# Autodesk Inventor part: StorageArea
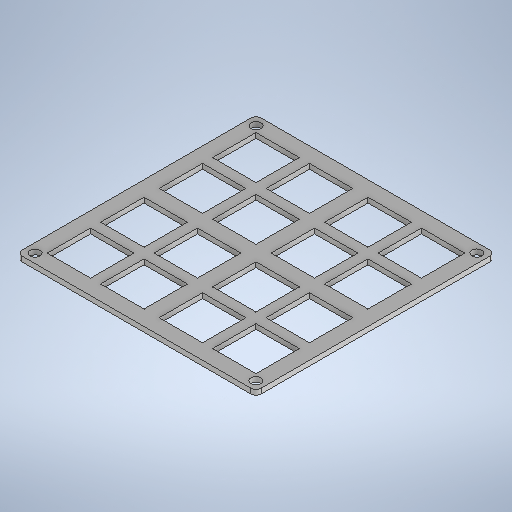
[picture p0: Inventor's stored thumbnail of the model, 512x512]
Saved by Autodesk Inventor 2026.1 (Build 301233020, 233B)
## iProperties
Created: 2026-10
Part Number: StorageArea
Material: Generic
Document SubType Name: Modeling
Designer: hp
Density: 1 g/cm^3
Appearance: Default
d6: 43.000 mm
d7: 43.000 mm
d20: 5.000 mm
d21: 0.00 deg
d26: 2.000 ul
d28: 111.000 mm
d29: 2.000 ul
d31: 111.000 mm
d34: 2.000 ul
d36: 53.000 mm
d37: 2.000 ul
d39: 53.000 mm
StorageThickness: 15.000 mm
d43: 15.000 mm
d44: 15.000 mm
d45: 15.000 mm
d46: 5.000 mm
d47: 10.000 mm
d48: 9.000 mm
d49: 9.000 mm
d51: 10.000 mm
d52: 0.00 deg
Author: hp
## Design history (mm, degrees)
sketch "Sketch1"
  geometry: L1 (-103.5, 60.5)-(-60.5, 60.5); L2 (-60.5, 60.5)-(-60.5, 103.5); L3 (-60.5, 103.5)-(-103.5, 103.5); L4 (-103.5, 103.5)-(-103.5, 60.5); L5 (-103.5, -50.5)-(-60.5, -50.5); L6 (-60.5, -50.5)-(-60.5, -7.5); L7 (-60.5, -7.5)-(-103.5, -7.5); L8 (-103.5, -7.5)-(-103.5, -50.5); L9 (7.5, 60.5)-(50.5, 60.5); L10 (50.5, 60.5)-(50.5, 103.5); L11 (50.5, 103.5)-(7.5, 103.5); L12 (7.5, 103.5)-(7.5, 60.5); L13 (7.5, -50.5)-(50.5, -50.5); L14 (50.5, -50.5)-(50.5, -7.5); L15 (50.5, -7.5)-(7.5, -7.5); L16 (7.5, -7.5)-(7.5, -50.5); L17 (7.5, -103.5)-(50.5, -103.5); L18 (50.5, -103.5)-(50.5, -60.5); L19 (-103.5, 7.5)-(-60.5, 7.5); L20 (7.5, -60.5)-(7.5, -103.5); L21 (-60.5, -103.5)-(-60.5, -60.5); L22 (-60.5, -60.5)-(-103.5, -60.5); L23 (-103.5, -103.5)-(-60.5, -103.5); L24 (-103.5, -60.5)-(-103.5, -103.5); L25 (-103.5, 50.5)-(-103.5, 7.5); L26 (-60.5, 50.5)-(-103.5, 50.5); L27 (-60.5, 7.5)-(-60.5, 50.5); L28 (50.5, -60.5)-(7.5, -60.5); L29 (7.5, 7.5)-(50.5, 7.5); L30 (7.5, 50.5)-(7.5, 7.5); L31 (50.5, 50.5)-(7.5, 50.5); L32 (50.5, 7.5)-(50.5, 50.5); L33 (60.5, -50.5)-(103.5, -50.5); L34 (103.5, -50.5)-(103.5, -7.5); L35 (-50.5, 60.5)-(-7.5, 60.5); L36 (60.5, -7.5)-(60.5, -50.5); L37 (-7.5, -50.5)-(-7.5, -7.5); L38 (-7.5, -7.5)-(-50.5, -7.5); L39 (-50.5, -50.5)-(-7.5, -50.5); L40 (-50.5, -7.5)-(-50.5, -50.5); L41 (-50.5, 103.5)-(-50.5, 60.5); L42 (-7.5, 103.5)-(-50.5, 103.5); L43 (-7.5, 60.5)-(-7.5, 103.5); L44 (103.5, -7.5)-(60.5, -7.5); L45 (60.5, 60.5)-(103.5, 60.5); L46 (60.5, 103.5)-(60.5, 60.5); L47 (103.5, 103.5)-(60.5, 103.5); L48 (103.5, 60.5)-(103.5, 103.5); L49 (60.5, -103.5)-(103.5, -103.5); L50 (103.5, -103.5)-(103.5, -60.5); L51 (-50.5, 7.5)-(-7.5, 7.5); L52 (60.5, -60.5)-(60.5, -103.5); L53 (-7.5, -103.5)-(-7.5, -60.5); L54 (-7.5, -60.5)-(-50.5, -60.5); L55 (-50.5, -103.5)-(-7.5, -103.5); L56 (-50.5, -60.5)-(-50.5, -103.5); L57 (-50.5, 50.5)-(-50.5, 7.5); L58 (-7.5, 50.5)-(-50.5, 50.5); L59 (-7.5, 7.5)-(-7.5, 50.5); L60 (103.5, -60.5)-(60.5, -60.5); L61 (60.5, 7.5)-(103.5, 7.5); L62 (60.5, 50.5)-(60.5, 7.5); L63 (103.5, 50.5)-(60.5, 50.5); L64 (103.5, 7.5)-(103.5, 50.5)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; C1 r 5 at (-109.5, 109.5); C2 r 5 at (109.5, 109.5); C3 r 5 at (-109.5, -109.5); C4 r 5 at (109.5, -109.5); 34 further points
  constraints: 140 end point, 5 midpoint, 4 centre point, 4 collinear, 4 horizontal, 4 parallel, 3 symmetric about line, 2 perpendicular, 2 vertical, 1 coincident, 119 other
  dimensions: "d6" = 43 distance of L3.end L2.end; "d7" = 43 distance of L2.end L1.end; "d28" = 111 distance of L1.start L5.start (derived); "d31" = 111 distance of L1.start L9.start (derived); "d36" = 53 distance of L1.end L19.end (computed from d7); "d39" = 53 distance of L1.end L35.end (computed from d7); "StorageThickness" = 15 distance between parallel lines of L24 L68; "d43" = 15 distance between parallel lines of L17 L67 (derived); "d44" = 15 distance between parallel lines of L64 L66 (derived); "d45" = 15 distance between parallel lines of L11 L65 (derived); "d47" = 10 diameter of C1; "d48" = 9 distance from line of L65 C1.centre (= d49); "d49" = 9 distance from line of L68 C1.centre
  node "Sketch Rectangular Pattern1" dims "d28" = 111 (derived), "d31" = 111 (derived)
  node "Sketch Rectangular Pattern2" dims "d36" = 53 (computed from d7), "d39" = 53 (computed from d7)
extrude "Extrusion1" new body sketch "Sketch1" distance "d20" = 5; taper "d21" = 0 deg
fillet "Fillet2" dims "d46" = 5
extrude "Extrusion2" cut sketch "Sketch1" distance "d51" = 10; taper "d52" = 0 deg
body "Solid1"
other parameters: "d26" = 2, "d29" = 2, "d34" = 2, "d37" = 2
